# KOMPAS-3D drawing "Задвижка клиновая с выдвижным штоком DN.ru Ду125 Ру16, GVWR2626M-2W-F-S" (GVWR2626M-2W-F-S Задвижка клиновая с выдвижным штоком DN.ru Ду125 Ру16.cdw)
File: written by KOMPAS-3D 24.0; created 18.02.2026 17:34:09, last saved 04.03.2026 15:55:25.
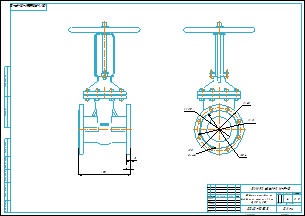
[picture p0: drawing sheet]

Document properties: Автор: R2D2; Форматы листов документа: A2; Полное имя файла: GVWR2626M-2W-F-S Задвижка клиновая с выдвижным штоком DN.ru Ду125 Ру16.m3d; Масса: 40; Наименование: Задвижка клиновая с выдвижным штоком DN.ru Ду125 Ру16; Количество листов документа: 1; Примечание: D040-10503

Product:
- Part/product: Задвижка клиновая с выдвижным штоком DN.ru Ду125 Ру16  | designation GVWR2626M-2W-F-S
    Масса: 40
    Раздел спецификации: Прочие изделия
    Примечание: D040-10503

Referenced files in E:\Работа\Зайцев\Для компаса\: чертеж DN.ru А3.cdt
Referenced files in E:\Работа\Зайцев\GVWR2626M-2W-F-S Задвижка клиновая с выдвижным штоком DN.ru Ду50-300 Ру16\DN125\: GVWR2626M-2W-F-S Задвижка клиновая с выдвижным штоком DN.ru Ду125 Ру16.m3d
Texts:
  чертеж DN.ru А3.cdt
  Задвижка клиновая с
  выдвижным штоком DN.ru
  Ду125 Ру16
  GVWR2626M-2W-F-S
  Задвижка клиновая с выдвижным штоком DN.ru Ду125 Ру16
  GVWR2626M-2W-F-S Задвижка клиновая с выдвижным штоком DN.ru Ду125 Ру16
Dimensions and other numbers on the sheet: 1:2,5; 0; 1; 2; 40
